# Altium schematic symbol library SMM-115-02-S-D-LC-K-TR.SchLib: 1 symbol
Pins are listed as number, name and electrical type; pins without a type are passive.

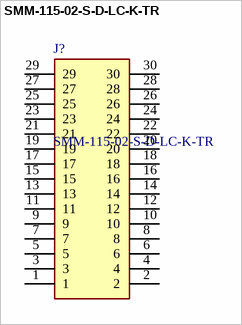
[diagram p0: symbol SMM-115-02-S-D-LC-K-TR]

## SMM-115-02-S-D-LC-K-TR
designator J?
Headers & Wire Housings Low Profile Socket Strips, 2.00 mm Pitch; Manufacturer_Name: SAMTEC; Geometry.Height: 3.81mm
footprint SMM11502SDLCKTR
pins: 1, 2, 3, 4, 5, 6, 7, 8, 9, 10, 11, 12, 13, 14, 15, 16, 17, 18, 19, 20, 21, 22, 23, 24, 25, 26, 27, 28, 29, 30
